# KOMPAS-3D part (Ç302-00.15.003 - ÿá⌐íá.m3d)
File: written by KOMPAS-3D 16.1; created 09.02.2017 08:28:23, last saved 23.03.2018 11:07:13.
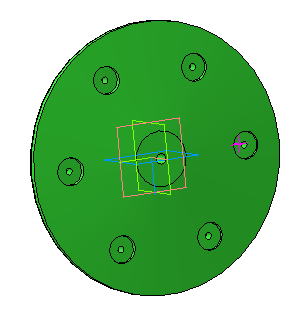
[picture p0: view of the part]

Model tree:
1. Эскиз:7
2. Операция вращения:1
     Угол 1 = 360
3. Скругление:16
     Радиус = 4
4. Отверстие:1
     Глубина выреза = 15; Диаметр отверстия = 7.8; Угол конуса торца = 118
5. Эскиз:22
6. Отверстие:2
     Глубина выреза = 9; Диаметр отверстия = 6; Угол конуса торца = 118; Координата Y = -50
7. Массив по концентрической сетке:1  (with: Отверстие:2, Эскиз:22)  (4 pattern instances)
     Геометрический массив = 3; Шаг 2 = 360
8. Эскиз:23
9. Отверстие:3
     Глубина выреза = 15; Диаметр отверстия = 5; Угол конуса торца = 118; Координата Y = 70
10. Эскиз:24
11. Вырезать элемент выдавливания:3
     Расстояние 1 = 7
12. Массив по концентрической сетке:2  (with: Отверстие:3, Эскиз:23, Вырезать элемент выдавливания:3, Эскиз:24)  (6 pattern instances)
     Геометрический массив = 5; Шаг 2 = 360
13. Фаска:1  (labels: Полипропилен  ГОСТ 26996-86)
     Угол = 45; Длина 1 = 1; Длина 2 = 1

Expressions: (250-60)/2+3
